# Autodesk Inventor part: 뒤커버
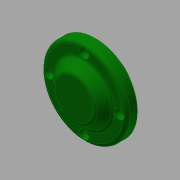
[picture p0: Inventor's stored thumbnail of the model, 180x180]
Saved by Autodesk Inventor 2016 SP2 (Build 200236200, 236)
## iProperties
Created: 2017-08
Part Number: 뒤커버
Material: 알루미늄 6061
Document SubType Name: Modeling
Designer: mduedu
Density: 1 g/cm^3
Appearance: 진녹색
Author: mduedu
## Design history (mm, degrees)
sketch "스케치1"
  geometry: C1 r 35 at (0, 0); 1 further point
  constraints: 1 centre point, 1 coincident
  dimensions: "d0" = 70 diameter of C1
extrude "돌출1" new body sketch "스케치1" distance "d1" = 10; taper "d2" = 0 deg
sketch "스케치2"
  geometry: C1 r 24 at (0, 0); 1 further point
  constraints: 1 centre point, 1 coincident
  dimensions: "d3" = 48 diameter of C1
node "작업 평면1"
sketch "스케치3"
  geometry: C1 r 17 at (0, 0); 1 further point
  constraints: 1 centre point, 1 coincident
  dimensions: "d5" = 34 diameter of C1
feature "로프트1" sketch "스케치3" dims "d6" = 0, "d7" = 90 deg, "d8" = 0, "d9" = 90 deg
sketch "스케치4"
  geometry: C1 r 24 at (0, 0) reference; 1 further point
extrude "돌출2" join sketch "스케치4" distance "d10" = 8; taper "d11" = 0 deg
hole "구멍1" diameter "d14" = 40; stored, may be unused: countersink angle "d18" = 90 deg, drill point angle "d20" = 0 deg; dims "d12" = 10, "d13" = 10, "d15" = 6, "d16" = 4, "d17" = 2, "d19" = 12
hole "구멍2" diameter "d23" = 34; stored, may be unused: countersink angle "d27" = 90 deg, drill point angle "d29" = 0 deg; dims "d24" = 6, "d25" = 4, "d26" = 2, "d28" = 6, "d62" = 10, "d63" = 10
chamfer "모따기1" distance "d39" = 1; stored, may be unused: second distance "d40" = 2, angle "d41" = 45 deg
fillet "모깎기1" dims "d42" = 0.3
fillet "모깎기2" dims "d43" = 3
sketch "스케치5" dims "d44" = 58
  geometry: 6 further points
  constraints: 2 vertical alignment, 1 coincident, 7 other
  dimensions: "d47" = 360 deg dimension on point (0, 0) point (0, 29) (derived)
sketch "스케치6"
  geometry: 4 further points
  constraints: 4 other
hole "구멍4" sketch "스케치6" at (0, 29), (-29, 0), (29, 0), (0, -29) diameter "d49" = 4.5; stored, may be unused: countersink angle "d53" = 90 deg, drill point angle "d55" = 0 deg; dims "d50" = 6, "d51" = 8, "d52" = 4.6, "d54" = 8
fillet "모깎기3" dims "d56" = 3
fillet "모깎기4" dims "d57" = 3
fillet "모깎기5" dims "d58" = 3
chamfer "모따기2" distance "d59" = 1; stored, may be unused: second distance "d60" = 2, angle "d61" = 45 deg
node "솔리드1"
other parameters: "d4" = 8
